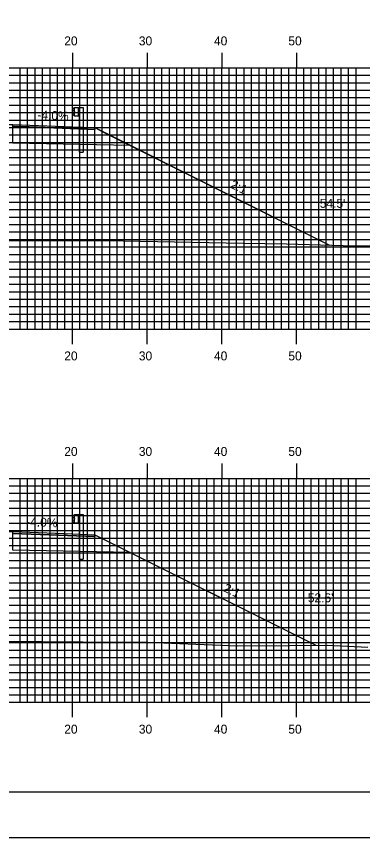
# Model space of a CAD drawing. Extents: x 1761397 to 1761741, y 442591 to 442811.
# Drawn here: x 1761575.7 to 1761622.1, y 442590.5 to 442700.5 of the extents above; entities that cross this region are included whole.
import ezdxf

# ---------------------------------------------------------------- set-up
doc = ezdxf.new("R2010")
doc.units = 0
for name, color, linetype in [('ANNOTATION', 7, 'Continuous'), ('BORDER', 7, 'Continuous'), ('D_Guardrail_Beam_Rt', 7, 'Continuous'), ('D_Roadway_Centerline', 7, 'Continuous'), ('D_Roadway_Edge_Shoulder', 7, 'Continuous'), ('D_Roadway_SlopeLines', 7, 'Continuous'), ('D_Roadway_SubGrade', 7, 'Continuous'), ('D_Text_Standard', 7, 'Continuous'), ('H_V ANNOTATION', 7, 'Continuous'), ('MAJOR', 7, 'Continuous'), ('MINOR', 7, 'Continuous'), ('PLOT BOUNDARY', 7, 'Continuous'), ('S_Roadway_Centerline', 7, 'Continuous')]:
    doc.layers.add(name, color=color, linetype=linetype)

msp = doc.modelspace()

# ---------------------------------------------------------------- linework, layer by layer
at = {"layer": 'BORDER'}
msp.add_lwpolyline([(1761413.64, 442596.67), (1761733.64, 442596.67), (1761733.64, 442806.67), (1761413.64, 442806.67)], close=True, dxfattribs=at)
at = {"layer": 'D_Guardrail_Beam_Rt'}
for p, q in [((1761583.42, 442688.25), (1761583.28, 442688.15)), ((1761583.28, 442688), (1761583.47, 442687.87)), ((1761583.47, 442687.67), (1761583.28, 442687.53)), ((1761583.28, 442687.39), (1761583.42, 442687.29)), ((1761583.51, 442688.27), (1761583.44, 442688.25)), ((1761583.51, 442688.35), (1761584.2, 442688.35)), ((1761583.51, 442687.18), (1761583.51, 442688.35)), ((1761583.51, 442687.8), (1761583.51, 442687.73)), ((1761584.03, 442688.35), (1761584.03, 442687.18)), ((1761584.14, 442688.35), (1761584.14, 442687.18)), ((1761584.2, 442688.35), (1761584.67, 442688.35)), ((1761584.2, 442688.35), (1761584.2, 442687.18)), ((1761584.67, 442688.35), (1761584.67, 442682.35)), ((1761583.44, 442687.28), (1761583.51, 442687.27)), ((1761584.2, 442687.18), (1761583.51, 442687.18)), ((1761584.18, 442682.35), (1761584.18, 442687.18)), ((1761584.18, 442682.35), (1761584.67, 442682.35)), ((1761583.42, 442633.71), (1761583.28, 442633.61)), ((1761583.28, 442633.47), (1761583.47, 442633.33)), ((1761583.51, 442633.73), (1761583.44, 442633.72)), ((1761583.51, 442633.82), (1761584.2, 442633.82)), ((1761583.51, 442632.65), (1761583.51, 442633.82)), ((1761584.03, 442633.82), (1761584.03, 442632.65)), ((1761584.14, 442633.82), (1761584.14, 442632.65)), ((1761584.2, 442633.82), (1761584.67, 442633.82)), ((1761584.2, 442633.82), (1761584.2, 442632.65)), ((1761584.67, 442633.82), (1761584.67, 442627.82)), ((1761583.47, 442633.13), (1761583.28, 442633)), ((1761583.28, 442632.85), (1761583.42, 442632.75)), ((1761583.44, 442632.75), (1761583.51, 442632.73)), ((1761583.51, 442633.27), (1761583.51, 442633.2)), ((1761584.2, 442632.65), (1761583.51, 442632.65)), ((1761584.18, 442627.82), (1761584.18, 442632.65)), ((1761584.18, 442627.82), (1761584.67, 442627.82))]:
    msp.add_line(p, q, dxfattribs=at)
for centre, major_axis, start_param, end_param in [((1761583.33, 442688.07), (-0.0877, 0), 5.323254, 7.243116), ((1761583.33, 442687.46), (-0.0877, 0), 5.323254, 7.243116), ((1761583.44, 442688.21), (-0.0417, 0), 4.907132, 5.323254), ((1761583.43, 442687.8), (0.0789, 0), 0, 0.959931), ((1761583.43, 442687.73), (0.0789, 0), 5.323254, 6.283185), ((1761583.44, 442687.32), (-0.0417, 0), 0.959931, 1.376053), ((1761583.33, 442633.54), (-0.0877, 0), 5.323254, 7.243116), ((1761583.44, 442633.68), (-0.0417, 0), 4.907132, 5.323254), ((1761583.33, 442632.93), (-0.0877, 0), 5.323254, 7.243116), ((1761583.44, 442632.79), (-0.0417, 0), 0.959931, 1.376053), ((1761583.43, 442633.27), (0.0789, 0), 0, 0.959931), ((1761583.43, 442633.2), (0.0789, 0), 5.323254, 6.283185)]:
    msp.add_ellipse(centre, major_axis=major_axis, ratio=0.995501, start_param=start_param, end_param=end_param, dxfattribs=at)
at = {"layer": 'D_Roadway_Centerline'}
for points in [[(1761512.91, 442671.12), (1761512.91, 442671.12), (1761520.88, 442675.1), (1761534.94, 442682.13), (1761534.95, 442682.14), (1761539.62, 442684.47), (1761540.24, 442684.78), (1761543.24, 442684.9), (1761543.24, 442684.9), (1761551.24, 442685.22), (1761557.66, 442685.45), (1761563.24, 442685.66), (1761563.24, 442685.66), (1761574.09, 442686.05), (1761575.24, 442686.09), (1761583.24, 442685.77), (1761586.24, 442685.65), (1761587.33, 442685.1), (1761590.99, 442683.27), (1761591, 442683.27), (1761610.09, 442673.72), (1761617.69, 442669.92), (1761617.7, 442669.92)], [(1761514.07, 442617.16), (1761514.08, 442617.17), (1761525.29, 442622.77), (1761534.85, 442627.55), (1761534.95, 442627.6), (1761534.97, 442627.61), (1761536.43, 442628.35), (1761540.24, 442630.25), (1761540.24, 442630.25), (1761543.24, 442630.37), (1761549.24, 442630.61), (1761551.22, 442630.69), (1761551.24, 442630.69), (1761563.2, 442631.12), (1761563.24, 442631.12), (1761563.28, 442631.12), (1761575.24, 442631.55), (1761583.24, 442631.23), (1761583.24, 442631.23), (1761586.23, 442631.11), (1761586.24, 442631.11), (1761590.73, 442628.87), (1761590.99, 442628.74), (1761615.83, 442616.32)]]:
    msp.add_lwpolyline(points, dxfattribs=at)
at = {"layer": 'D_Roadway_Edge_Shoulder'}
for points in [[(1761575.24, 442686.09), (1761583.24, 442685.77), (1761583.24, 442685.77), (1761586.24, 442685.65), (1761586.24, 442685.4), (1761575.24, 442685.84)], [(1761575.24, 442631.55), (1761583.24, 442631.23), (1761583.24, 442631.23), (1761586.24, 442631.11), (1761586.24, 442630.86), (1761575.24, 442631.3)]]:
    msp.add_lwpolyline(points, close=True, dxfattribs=at)
at = {"layer": 'D_Roadway_SlopeLines'}
for points in [[(1761586.24, 442685.65), (1761617.7, 442669.92)], [(1761586.24, 442631.11), (1761615.83, 442616.32)]]:
    msp.add_lwpolyline(points, dxfattribs=at)
at = {"layer": 'D_Roadway_SubGrade'}
for points in [[(1761575.24, 442685.42), (1761575.24, 442685.84), (1761586.24, 442685.4), (1761586.24, 442685.65), (1761590.99, 442683.27), (1761575.24, 442683.59)], [(1761575.24, 442630.89), (1761575.24, 442631.3), (1761586.24, 442630.86), (1761586.24, 442631.11), (1761590.99, 442628.74), (1761575.24, 442629.05)]]:
    msp.add_lwpolyline(points, close=True, dxfattribs=at)
at = {"layer": 'MAJOR'}
for p, q in [((1761583.24, 442695.67), (1761583.24, 442693.67)), ((1761593.24, 442695.67), (1761593.24, 442693.67)), ((1761603.24, 442695.67), (1761603.24, 442693.67)), ((1761613.24, 442695.67), (1761613.24, 442693.67)), ((1761423.24, 442693.67), (1761703.24, 442693.67)), ((1761423.24, 442693.67), (1761703.24, 442693.67)), ((1761583.24, 442658.67), (1761583.24, 442693.67)), ((1761593.24, 442658.67), (1761593.24, 442693.67)), ((1761603.24, 442658.67), (1761603.24, 442693.67)), ((1761613.24, 442658.67), (1761613.24, 442693.67)), ((1761423.24, 442688.67), (1761703.24, 442688.67)), ((1761423.24, 442683.67), (1761703.24, 442683.67)), ((1761423.24, 442678.67), (1761703.24, 442678.67)), ((1761423.24, 442673.67), (1761703.24, 442673.67)), ((1761423.24, 442668.67), (1761703.24, 442668.67)), ((1761423.24, 442663.67), (1761703.24, 442663.67)), ((1761423.24, 442658.67), (1761703.24, 442658.67)), ((1761423.24, 442658.67), (1761703.24, 442658.67)), ((1761583.24, 442656.66), (1761583.24, 442658.67)), ((1761593.24, 442656.66), (1761593.24, 442658.67)), ((1761603.24, 442656.66), (1761603.24, 442658.67)), ((1761613.24, 442656.66), (1761613.24, 442658.67)), ((1761583.24, 442640.67), (1761583.24, 442638.67)), ((1761593.24, 442640.67), (1761593.24, 442638.67)), ((1761603.24, 442640.67), (1761603.24, 442638.67)), ((1761613.24, 442640.67), (1761613.24, 442638.67)), ((1761423.24, 442638.67), (1761703.24, 442638.67)), ((1761423.24, 442638.67), (1761703.24, 442638.67)), ((1761583.24, 442608.67), (1761583.24, 442638.67)), ((1761593.24, 442608.67), (1761593.24, 442638.67)), ((1761603.24, 442608.67), (1761603.24, 442638.67)), ((1761613.24, 442608.67), (1761613.24, 442638.67)), ((1761423.24, 442633.67), (1761703.24, 442633.67)), ((1761423.24, 442628.67), (1761703.24, 442628.67)), ((1761423.24, 442623.67), (1761703.24, 442623.67)), ((1761423.24, 442618.67), (1761703.24, 442618.67)), ((1761423.24, 442613.67), (1761703.24, 442613.67)), ((1761423.24, 442608.67), (1761703.24, 442608.67)), ((1761423.24, 442608.67), (1761703.24, 442608.67)), ((1761583.24, 442606.66), (1761583.24, 442608.67)), ((1761593.24, 442606.66), (1761593.24, 442608.67)), ((1761603.24, 442606.66), (1761603.24, 442608.67)), ((1761613.24, 442606.66), (1761613.24, 442608.67))]:
    msp.add_line(p, q, dxfattribs=at)
at = {"layer": 'MINOR'}
for p, q in [((1761576.24, 442658.67), (1761576.24, 442693.67)), ((1761577.24, 442658.67), (1761577.24, 442693.67)), ((1761578.24, 442658.67), (1761578.24, 442693.67)), ((1761579.24, 442658.67), (1761579.24, 442693.67)), ((1761580.24, 442658.67), (1761580.24, 442693.67)), ((1761581.24, 442658.67), (1761581.24, 442693.67)), ((1761582.24, 442658.67), (1761582.24, 442693.67)), ((1761584.24, 442658.67), (1761584.24, 442693.67)), ((1761585.24, 442658.67), (1761585.24, 442693.67)), ((1761586.24, 442658.67), (1761586.24, 442693.67)), ((1761587.24, 442658.67), (1761587.24, 442693.67)), ((1761588.24, 442658.67), (1761588.24, 442693.67)), ((1761589.24, 442658.67), (1761589.24, 442693.67)), ((1761590.24, 442658.67), (1761590.24, 442693.67)), ((1761591.24, 442658.67), (1761591.24, 442693.67)), ((1761592.24, 442658.67), (1761592.24, 442693.67)), ((1761594.24, 442658.67), (1761594.24, 442693.67)), ((1761595.24, 442658.67), (1761595.24, 442693.67)), ((1761596.24, 442658.67), (1761596.24, 442693.67)), ((1761597.24, 442658.67), (1761597.24, 442693.67)), ((1761598.24, 442658.67), (1761598.24, 442693.67)), ((1761599.24, 442658.67), (1761599.24, 442693.67)), ((1761600.24, 442658.67), (1761600.24, 442693.67)), ((1761601.24, 442658.67), (1761601.24, 442693.67)), ((1761602.24, 442658.67), (1761602.24, 442693.67)), ((1761604.24, 442658.67), (1761604.24, 442693.67)), ((1761605.24, 442658.67), (1761605.24, 442693.67)), ((1761606.24, 442658.67), (1761606.24, 442693.67)), ((1761607.24, 442658.67), (1761607.24, 442693.67)), ((1761608.24, 442658.67), (1761608.24, 442693.67)), ((1761609.24, 442658.67), (1761609.24, 442693.67)), ((1761610.24, 442658.67), (1761610.24, 442693.67)), ((1761611.24, 442658.67), (1761611.24, 442693.67)), ((1761612.24, 442658.67), (1761612.24, 442693.67)), ((1761614.24, 442658.67), (1761614.24, 442693.67)), ((1761615.24, 442658.67), (1761615.24, 442693.67)), ((1761616.24, 442658.67), (1761616.24, 442693.67)), ((1761617.24, 442658.67), (1761617.24, 442693.67)), ((1761618.24, 442658.67), (1761618.24, 442693.67)), ((1761619.24, 442658.67), (1761619.24, 442693.67)), ((1761620.24, 442658.67), (1761620.24, 442693.67)), ((1761621.24, 442658.67), (1761621.24, 442693.67)), ((1761423.24, 442692.67), (1761703.24, 442692.67)), ((1761423.24, 442691.67), (1761703.24, 442691.67)), ((1761423.24, 442690.67), (1761703.24, 442690.67)), ((1761423.24, 442689.67), (1761703.24, 442689.67)), ((1761423.24, 442687.67), (1761703.24, 442687.67)), ((1761423.24, 442686.67), (1761703.24, 442686.67)), ((1761423.24, 442685.67), (1761703.24, 442685.67)), ((1761423.24, 442684.67), (1761703.24, 442684.67)), ((1761423.24, 442682.67), (1761703.24, 442682.67)), ((1761423.24, 442681.67), (1761703.24, 442681.67)), ((1761423.24, 442680.67), (1761703.24, 442680.67)), ((1761423.24, 442679.67), (1761703.24, 442679.67)), ((1761423.24, 442677.67), (1761703.24, 442677.67)), ((1761423.24, 442676.67), (1761703.24, 442676.67)), ((1761423.24, 442675.67), (1761703.24, 442675.67)), ((1761423.24, 442674.67), (1761703.24, 442674.67)), ((1761423.24, 442672.67), (1761703.24, 442672.67)), ((1761423.24, 442671.67), (1761703.24, 442671.67)), ((1761423.24, 442670.67), (1761703.24, 442670.67)), ((1761423.24, 442669.67), (1761703.24, 442669.67)), ((1761423.24, 442667.67), (1761703.24, 442667.67)), ((1761423.24, 442666.67), (1761703.24, 442666.67)), ((1761423.24, 442665.67), (1761703.24, 442665.67)), ((1761423.24, 442664.67), (1761703.24, 442664.67)), ((1761423.24, 442662.67), (1761703.24, 442662.67)), ((1761423.24, 442661.67), (1761703.24, 442661.67)), ((1761423.24, 442660.67), (1761703.24, 442660.67)), ((1761423.24, 442659.67), (1761703.24, 442659.67)), ((1761576.24, 442608.67), (1761576.24, 442638.67)), ((1761577.24, 442608.67), (1761577.24, 442638.67)), ((1761578.24, 442608.67), (1761578.24, 442638.67)), ((1761579.24, 442608.67), (1761579.24, 442638.67)), ((1761580.24, 442608.67), (1761580.24, 442638.67)), ((1761581.24, 442608.67), (1761581.24, 442638.67)), ((1761582.24, 442608.67), (1761582.24, 442638.67)), ((1761584.24, 442608.67), (1761584.24, 442638.67)), ((1761585.24, 442608.67), (1761585.24, 442638.67)), ((1761586.24, 442608.67), (1761586.24, 442638.67)), ((1761587.24, 442608.67), (1761587.24, 442638.67)), ((1761588.24, 442608.67), (1761588.24, 442638.67)), ((1761589.24, 442608.67), (1761589.24, 442638.67)), ((1761590.24, 442608.67), (1761590.24, 442638.67)), ((1761591.24, 442608.67), (1761591.24, 442638.67)), ((1761592.24, 442608.67), (1761592.24, 442638.67)), ((1761594.24, 442608.67), (1761594.24, 442638.67)), ((1761595.24, 442608.67), (1761595.24, 442638.67)), ((1761596.24, 442608.67), (1761596.24, 442638.67)), ((1761597.24, 442608.67), (1761597.24, 442638.67)), ((1761598.24, 442608.67), (1761598.24, 442638.67)), ((1761599.24, 442608.67), (1761599.24, 442638.67)), ((1761600.24, 442608.67), (1761600.24, 442638.67)), ((1761601.24, 442608.67), (1761601.24, 442638.67)), ((1761602.24, 442608.67), (1761602.24, 442638.67)), ((1761604.24, 442608.67), (1761604.24, 442638.67)), ((1761605.24, 442608.67), (1761605.24, 442638.67)), ((1761606.24, 442608.67), (1761606.24, 442638.67)), ((1761607.24, 442608.67), (1761607.24, 442638.67)), ((1761608.24, 442608.67), (1761608.24, 442638.67)), ((1761609.24, 442608.67), (1761609.24, 442638.67)), ((1761610.24, 442608.67), (1761610.24, 442638.67)), ((1761611.24, 442608.67), (1761611.24, 442638.67)), ((1761612.24, 442608.67), (1761612.24, 442638.67)), ((1761614.24, 442608.67), (1761614.24, 442638.67)), ((1761615.24, 442608.67), (1761615.24, 442638.67)), ((1761616.24, 442608.67), (1761616.24, 442638.67)), ((1761617.24, 442608.67), (1761617.24, 442638.67)), ((1761618.24, 442608.67), (1761618.24, 442638.67)), ((1761619.24, 442608.67), (1761619.24, 442638.67)), ((1761620.24, 442608.67), (1761620.24, 442638.67)), ((1761621.24, 442608.67), (1761621.24, 442638.67)), ((1761423.24, 442637.67), (1761703.24, 442637.67)), ((1761423.24, 442636.67), (1761703.24, 442636.67)), ((1761423.24, 442635.67), (1761703.24, 442635.67)), ((1761423.24, 442634.67), (1761703.24, 442634.67)), ((1761423.24, 442632.67), (1761703.24, 442632.67)), ((1761423.24, 442631.67), (1761703.24, 442631.67)), ((1761423.24, 442630.67), (1761703.24, 442630.67)), ((1761423.24, 442629.67), (1761703.24, 442629.67)), ((1761423.24, 442627.67), (1761703.24, 442627.67)), ((1761423.24, 442626.67), (1761703.24, 442626.67)), ((1761423.24, 442625.67), (1761703.24, 442625.67)), ((1761423.24, 442624.67), (1761703.24, 442624.67)), ((1761423.24, 442622.67), (1761703.24, 442622.67)), ((1761423.24, 442621.67), (1761703.24, 442621.67)), ((1761423.24, 442620.67), (1761703.24, 442620.67)), ((1761423.24, 442619.67), (1761703.24, 442619.67)), ((1761423.24, 442617.67), (1761703.24, 442617.67)), ((1761423.24, 442616.67), (1761703.24, 442616.67)), ((1761423.24, 442615.67), (1761703.24, 442615.67)), ((1761423.24, 442614.67), (1761703.24, 442614.67)), ((1761423.24, 442612.67), (1761703.24, 442612.67)), ((1761423.24, 442611.67), (1761703.24, 442611.67)), ((1761423.24, 442610.67), (1761703.24, 442610.67)), ((1761423.24, 442609.67), (1761703.24, 442609.67))]:
    msp.add_line(p, q, dxfattribs=at)
at = {"layer": 'PLOT BOUNDARY'}
msp.add_lwpolyline([(1761397.45, 442590.55), (1761737.45, 442590.55), (1761737.45, 442810.55), (1761397.45, 442810.55)], close=True, dxfattribs=at)
at = {"layer": 'S_Roadway_Centerline'}
for points in [[(1761505.08, 442671.17), (1761525.57, 442671.03), (1761527.25, 442671), (1761529.25, 442671.06), (1761546.94, 442671.2), (1761555.31, 442671.06), (1761562.19, 442671.37), (1761568.45, 442670.7), (1761574.37, 442670.52), (1761581.2, 442670.52), (1761590.04, 442670.49), (1761606.12, 442670.18), (1761611.91, 442670.09), (1761621.05, 442669.82), (1761632.88, 442669.81)], [(1761502.88, 442617.47), (1761522.82, 442616.92), (1761525.19, 442616.95), (1761527.85, 442616.93), (1761540.5, 442616.92), (1761546.09, 442616.92), (1761546.91, 442616.91), (1761547.95, 442616.91), (1761559.54, 442616.7), (1761568.56, 442616.84), (1761573.96, 442616.85), (1761589.96, 442616.74), (1761593.35, 442616.73), (1761597.6, 442616.54), (1761605.31, 442616.22), (1761612.37, 442616.27), (1761617.39, 442616.34), (1761622.81, 442616.06)]]:
    msp.add_lwpolyline(points, dxfattribs=at)

# ---------------------------------------------------------------- texts
at = {"layer": 'ANNOTATION'}
for s, rotation, p in [('-4.0%', 357.7093, (1761578.53, 442686.76)), ('2:1', 333.4331, (1761604.28, 442677.66)), ('-4.0%', 357.7094, (1761577.03, 442632.28)), ('2:1', 333.4355, (1761603.35, 442623.6))]:
    msp.add_text(s, height=1.2, rotation=rotation, dxfattribs=at).set_placement(p)
at = {"layer": 'D_Text_Standard'}
for s, p in [("54.5'", (1761616.38, 442674.91)), ("52.6'", (1761614.78, 442622.07))]:
    msp.add_text(s, height=1.2, dxfattribs=at).set_placement(p)
at = {"layer": 'H_V ANNOTATION'}
for s, p in [('20', (1761582.15, 442696.67)), ('30', (1761592.14, 442696.67)), ('40', (1761602.21, 442696.67)), ('50', (1761612.17, 442696.67)), ('20', (1761582.15, 442654.47)), ('30', (1761592.14, 442654.47)), ('40', (1761602.21, 442654.47)), ('50', (1761612.17, 442654.47)), ('20', (1761582.15, 442641.67)), ('30', (1761592.14, 442641.67)), ('40', (1761602.21, 442641.67)), ('50', (1761612.17, 442641.67)), ('20', (1761582.15, 442604.47)), ('30', (1761592.14, 442604.47)), ('40', (1761602.21, 442604.47)), ('50', (1761612.17, 442604.47))]:
    msp.add_text(s, height=1.2, dxfattribs=at).set_placement(p)

doc.saveas('drawing.dxf')
